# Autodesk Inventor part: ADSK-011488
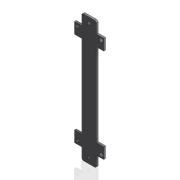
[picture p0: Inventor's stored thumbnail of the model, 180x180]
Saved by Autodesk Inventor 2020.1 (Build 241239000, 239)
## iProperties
Created: 2000-02
Part Number: ADSK-011488
Material: RA HRS
Description: PLT-06,FH,CP,02,171,040,MNT,CYLINDER
Document SubType Name: Modeling
Designer: cmcgourin
Density: 7.83 g/cm^3
Appearance: Métal - Acier
Mass: 1180.95 g
Surface Area: 582.509 cm^2
Volume: 150.824 cm^3
Control State: 0
Checked Out: False
Master: False
Shininess: 0.0
Length Units: 11269
Angle Units: 11279
Time Units: 11290
Mass Units: 11283
Length Display Precision: 3
Angle Display Precision: 2
Compacted: True
material desc: FLAT,HRS,0.250X4.000
Cutlength: 17.13
Material_Number: A084338
Dimensions: 100x435x6 mm
Mass: 1,181 kg
DocNumber: ADSK-011488.ipt
Folder: 01 - Themengebiete\Simplification\01 - Packaging machine\
VDS_Category: 3D Komponenten
Density: 0.0
Volumn: 0.0
Area: 0.0
PropertySet Name: Model Information
Author: cmcgourin
Revision Number: -
Title: plate
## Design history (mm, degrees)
node "Solide1"
  node "Extrusion1" dims "d3" = 6, "d4" = 0
  node "Fillet1" dims "d29" = 6
  node "Hole1" dims "d33" = 9, "d34" = 9.525, "d35" = 6.35, "d36" = 60 deg, "d37" = 19.05, "d38" = 118 deg, "d43" = 6
sketch "Sketch1"
  geometry: L1 (50, 0)-(0, 0); L2 (0, -435)-(50, -435); L3 (0, -38.5)-(0, 0); L4 (50, -38.5)-(50, 0); L5 (0, -76.5)-(0, -358.5); L6 (0, -76.5)-(-25, -76.5); L7 (-25, -396.5)-(-25, -358.5); L8 (75, -358.5)-(75, -396.5); L9 (-25, -358.5)-(0, -358.5); L10 (50, -358.5)-(75, -358.5); L11 (0, -396.5)-(0, -435); L12 (50, -435)-(50, -396.5); L13 (-25, -396.5)-(0, -396.5); L14 (50, -396.5)-(75, -396.5); L15 (0, -38.5)-(-25, -38.5); L16 (-25, -38.5)-(-25, -76.5); L17 (50, -38.5)-(75, -38.5); L18 (75, -38.5)-(75, -76.5); L19 (75, -76.5)-(50, -76.5); L20 (50, -19.05)-(50, -38.5); L21 (50, -76.5)-(50, -358.5); L22 (25, 0)-(25, -435); 1 further point
  constraints: 44 end point, 7 parallel, 6 equal length, 5 perpendicular, 3 collinear, 2 midpoint, 1 coincident, 1 horizontal, 1 other
  dimensions: "d16" = 435 distance between parallel lines of L1 L2; "d17" = 38 distance between parallel lines of L9 L13 (= d26); "d19" = 38.5 distance between parallel lines of L13 L2 (= d22); "d20" = 38 distance between parallel lines of L10 L14 (= d26); "d21" = 50 distance between parallel lines of L3 L4; "d22" = 38.5 distance between parallel lines of L1 L17; "d25" = 38 distance between parallel lines of L15 L6 (= d26); "d26" = 38 distance between parallel lines of L17 L19; "d27" = 50 distance between parallel lines of L12 L11; "d28" = 50 distance between parallel lines of L21 L5 (= d21); "d41" = 100 distance between parallel lines of L16 L18
sketch "Sketch4"
  geometry: L1 (66.25, -57.5)-(-16.25, -57.5); L2 (-16.25, -57.5)-(-16.25, -377.5); L3 (-16.25, -377.5)-(66.25, -377.5); L4 (66.25, -377.5)-(66.25, -57.5); L5 (50, -76.5)-(50, -358.5) reference; L6 (6, 0)-(44, 0) reference; 8 further points
  constraints: 8 end point, 4 coincident, 4 midpoint, 2 parallel, 1 horizontal, 1 horizontal alignment, 1 perpendicular, 1 vertical alignment
  dimensions: "d44" = 320 distance of L3.end L1.start; "d45" = 82.5 distance of L1.start L1.end
hole "Bohrung2" sketch "Sketch4" at (66.25, -57.5), (-16.25, -57.5), (66.25, -377.5), (-16.25, -377.5) diameter "d46" = 9; stored, may be unused: countersink angle "d50" = 90 deg, drill point angle "d52" = 118 deg; dims "d47" = 6, "d48" = 20, "d49" = 2, "d51" = 8
sketch "Sketch3"
  geometry: L1 (6, 0)-(44, 0) reference; L2 (25, -19)-(25, -416); L3 (50, -76.5)-(50, -358.5) reference; 3 further points
  constraints: 3 midpoint, 2 end point, 2 vertical alignment, 1 horizontal alignment, 1 vertical
  dimensions: "d42" = 397 distance of L2.start L2.end
node "Corps solides"
node "Corps surfaciques"
other parameters: "d8" = 25.4, "d9" = 25.4, "d10" = 50.8, "d15" = 50.8
